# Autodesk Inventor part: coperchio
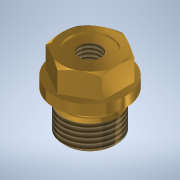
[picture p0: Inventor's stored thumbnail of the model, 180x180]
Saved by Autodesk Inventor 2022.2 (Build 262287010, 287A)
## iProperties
Created: 2014-01
Part Number: coperchio
Document SubType Name: Modeling
Designer: UTENTE
Density: 8.47 g/cm^3
Material: Ottone, Giallo chiaro
Appearance: Ottone - Satinato
Author: UTENTE
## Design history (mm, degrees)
sketch "Schizzo1"
  geometry: C1 r 12.7 at (0, 0); 1 further point
  constraints: 1 centre point, 1 coincident
  dimensions: "d0" = 25.4 diameter of C1
extrude "Estrusione1" new body sketch "Schizzo1" distance "d1" = 9; taper "d2" = 0 deg
chamfer "Smusso1" distance "d3" = 1; stored, may be unused: second distance "d4" = 1.7, angle "d5" = 30 deg
sketch "Schizzo2"
  geometry: L1 (-11, 6.351)-(0, 12.702); L2 (0, 12.702)-(11, 6.351); L3 (11, 6.351)-(11, -6.351); L4 (11, -6.351)-(0, -12.702); L5 (0, -12.702)-(-11, -6.351); L6 (-11, -6.351)-(-11, 6.351); C1 r 16.553 at (0, 0); 2 further points
  constraints: 12 end point, 1 centre point, 1 coincident, 1 midpoint, 13 other
extrude "Estrusione2" cut sketch "Schizzo2" distance "d6" = 9; taper "d7" = 0 deg
sketch "Schizzo3"
  geometry: C1 r 14 at (0, 0); A1 r 12.7 centre (0, 0) between (10.997, -6.353) and (11, -6.347) reference
  constraints: 1 centre point, 1 coincident
extrude "Estrusione3" join sketch "Schizzo3" distance "d9" = 4; taper "d10" = 0 deg
sketch "Schizzo4"
  geometry: C1 r 14 at (0, 0) reference; C2 r 8.5 at (0, 0)
  constraints: 1 centre point, 1 coincident
extrude "Estrusione4" join sketch "Schizzo4" distance "d12" = 4; taper "d13" = 0 deg
sketch "Schizzo5"
  geometry: C1 r 8.5 at (0, 0) reference; C2 r 10.5 at (0, 0)
  constraints: 1 centre point, 1 coincident
  dimensions: "d14" = 21 diameter of C2
extrude "Estrusione5" join sketch "Schizzo5" distance "d15" = 11; taper "d16" = 0 deg
chamfer "Smusso2" distance "d17" = 1; stored, may be unused: second distance "d18" = 1.7, angle "d19" = 30 deg
feature "Filettatura1" dims "d20" = 10, "d21" = 0
fillet "Raccordo1" dims "d22" = 0.5
sketch "Schizzo6"
  geometry: C1 r 8.25 at (0, 0); A1 r 11 centre (0, 0) between (-5.5, -9.526) and (5.5, -9.526) reference
  constraints: 1 centre point, 1 coincident
extrude "Estrusione6" cut sketch "Schizzo6" distance "d24" = 1; taper "d25" = 0 deg
sketch "Schizzo7"
  geometry: C1 r 8.25 at (0, 0) reference
hole "Hole1" diameter "d28" = 8.376; stored, may be unused: countersink angle "d32" = 90 deg, drill point angle "d34" = 118 deg; dims "d26" = 10, "d27" = 10, "d29" = 6, "d30" = 4, "d31" = 2, "d33" = 40
chamfer "Smusso3" distance "d35" = 1; stored, may be unused: second distance "d36" = 2, angle "d37" = 45 deg
node "Solido1"
